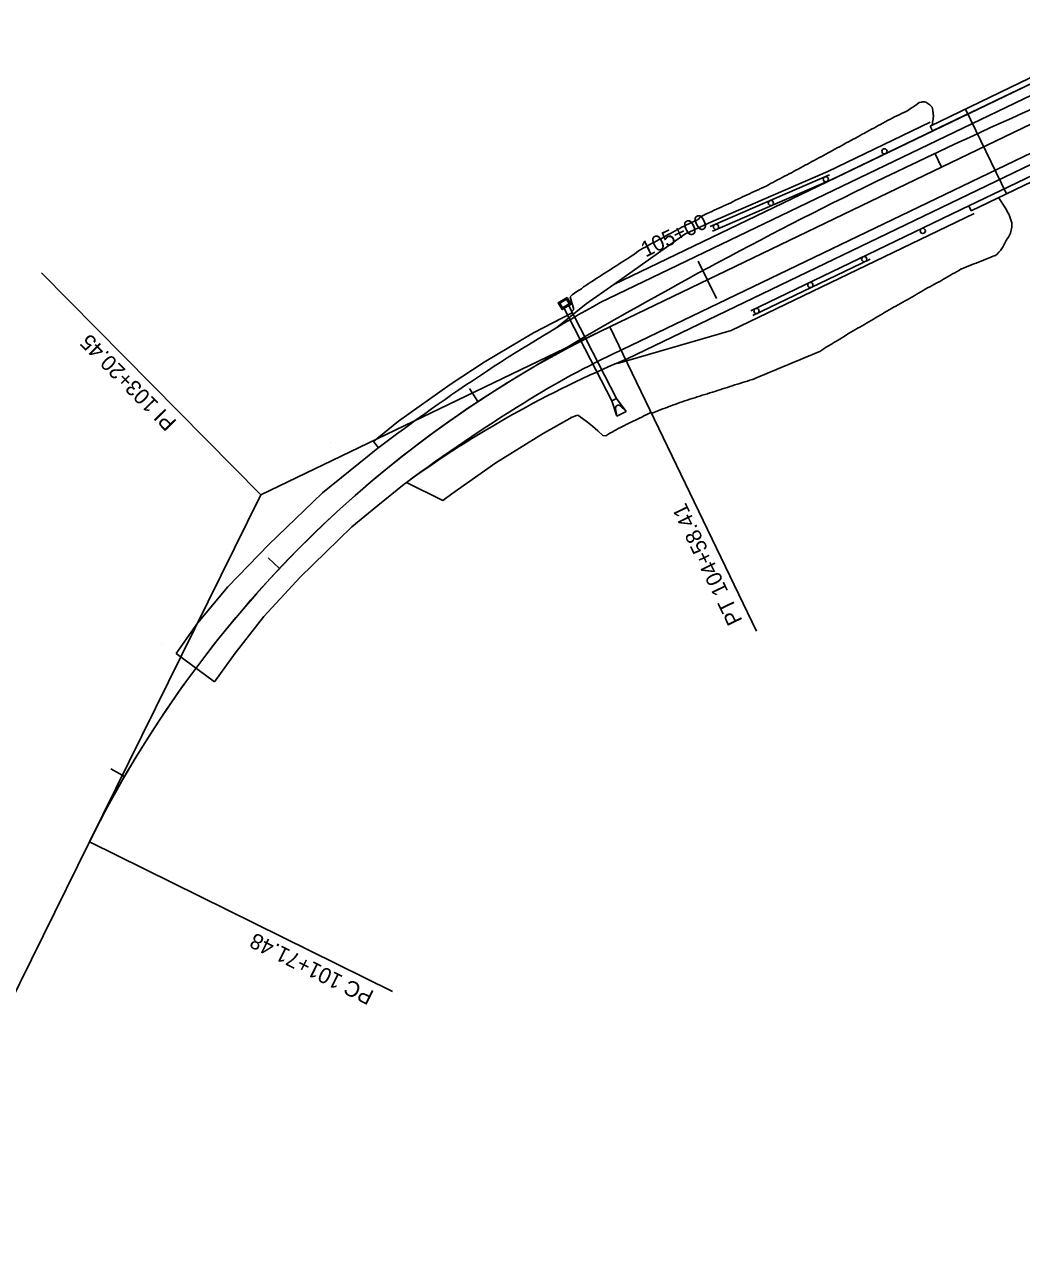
# Model space of a CAD drawing. Extents: x 834421 to 837111, y 495679 to 497078.
# Drawn here: x 835026.1 to 835409.7, y 496460 to 496928.3 of the extents above; entities that cross this region are included whole.
import ezdxf

# ---------------------------------------------------------------- set-up
doc = ezdxf.new("R2010")
doc.units = 0
for name, color, linetype in [('43', 7, 'Continuous'), ('EXISTING CENTERLINE', 7, 'Continuous'), ('R_Bridge', 7, 'Continuous'), ('R_Drainage', 7, 'Continuous'), ('R_Guardrail', 7, 'Continuous'), ('R_Horz Alg', 7, 'Continuous'), ('R_Horz Alg Annot', 7, 'Continuous'), ('R_Horz Alg Stationing', 7, 'Continuous'), ('R_Proposed Const Limits', 7, 'Continuous'), ('R_Proposed Road', 7, 'Continuous'), ('R_Shld_GR', 7, 'Continuous'), ('R_Shoulder', 7, 'Continuous'), ('Transportation__x002e__STATEWIDE_HIGHWAY_LOGMILES_AHTD_point', 7, 'Continuous')]:
    doc.layers.add(name, color=color, linetype=linetype)

msp = doc.modelspace()

# ---------------------------------------------------------------- linework, layer by layer
at = {"layer": '43'}
for p, q in [((835252.05, 496783.43), (835253.83, 496784.34)), ((835252.05, 496783.43), (835253.96, 496777.53)), ((835253.83, 496784.34), (835257.52, 496779.36)), ((835253.96, 496777.53), (835253.47, 496780.42)), ((835253.96, 496777.53), (835257.52, 496779.36)), ((835257.52, 496779.36), (835255.45, 496781.44))]:
    msp.add_line(p, q, dxfattribs=at)
msp.add_arc((835254.62, 496780.62), 1.17, 44.7462, 189.6864, dxfattribs=at)
at = {"layer": 'EXISTING CENTERLINE'}
msp.add_line((834975.23, 496460.02), (835051.16, 496613.79), dxfattribs=at)
for centre, radius, start, end in [((836126.37, 495283.19), 1762.95, 111.78793, 121.11124), ((835438.89, 496422.34), 432.42, 121.1112, 153.7219)]:
    msp.add_arc(centre, radius, start, end, dxfattribs=at)
at = {"layer": 'R_Bridge'}
for p, q in [((835374.54, 496889.18), (835455.78, 496928.29)), ((835375.46, 496887.26), (835456.71, 496926.37)), ((835403.85, 496863.06), (835388.13, 496895.72)), ((835389.34, 496858.43), (835470.58, 496897.54)), ((835390.26, 496856.51), (835471.51, 496895.62)), ((835375.46, 496887.26), (835374.54, 496889.18)), ((835390.26, 496856.51), (835389.34, 496858.43))]:
    msp.add_line(p, q, dxfattribs=at)
at = {"layer": 'R_Drainage'}
for p, q in [((835235.22, 496820.53), (835253.83, 496784.34)), ((835233.51, 496819.49), (835252.05, 496783.43))]:
    msp.add_line(p, q, dxfattribs=at)
for points in [[(835234.84, 496823.22), (835236.39, 496820.65), (835232.97, 496818.58), (835231.42, 496821.15)], [(835234.67, 496822.53), (835235.71, 496820.82), (835233.14, 496819.27), (835232.11, 496820.98)]]:
    msp.add_lwpolyline(points, close=True, dxfattribs=at)
at = {"layer": 'R_Guardrail'}
for p, q in [((835336.66, 496868.58), (835376.08, 496887.56)), ((835335.79, 496870.39), (835289.87, 496850.5)), ((835336.66, 496868.58), (835290.74, 496848.7)), ((835350.54, 496839.75), (835389.96, 496858.73)), ((835305.48, 496818.06), (835350.54, 496839.75)), ((835306.35, 496816.26), (835351.4, 496837.95))]:
    msp.add_line(p, q, dxfattribs=at)
for centre in [(835356.95, 496879.46), (835334.39, 496868.69), (835313.26, 496859.54), (835292.14, 496850.4), (835371.69, 496848.82), (835349.17, 496837.98), (835328.44, 496828.01), (835307.72, 496818.03)]:
    msp.add_circle(centre, 1, dxfattribs=at)
at = {"layer": 'R_Horz Alg'}
for p, q in [((835251.33, 496811.97), (835458.2, 496911.55)), ((835251.33, 496811.97), (835458.2, 496911.55)), ((834975.23, 496460.02), (835051.15, 496613.79)), ((834975.23, 496460.02), (835051.15, 496613.79))]:
    msp.add_line(p, q, dxfattribs=at)
msp.add_arc((835438.88, 496422.34), 432.42, 115.7042, 153.7222, dxfattribs=at)
msp.add_arc((835438.88, 496422.34), 432.42, 115.7042, 153.7222, dxfattribs=at)
at = {"layer": 'R_Horz Alg Annot'}
for p, q in [((835251.33, 496811.97), (835460.14, 496912.48)), ((834975.23, 496460.02), (835051.15, 496613.79))]:
    msp.add_line(p, q, dxfattribs=at)
for points in [[(835117.1, 496747.36), (835032.67, 496832.64)], [(835051.15, 496613.79), (835117.1, 496747.36), (835251.33, 496811.97)], [(835251.33, 496811.97), (835307.71, 496694.84)], [(835051.15, 496613.79), (835167.71, 496556.23)]]:
    msp.add_lwpolyline(points, dxfattribs=at)
msp.add_arc((835438.88, 496422.34), 432.42, 115.7042, 153.7222, dxfattribs=at)
at = {"layer": 'R_Horz Alg Stationing'}
for points in [[(835376.3, 496878.79), (835378.91, 496873.38)], [(835285.33, 496837.22), (835292.27, 496822.8)], [(835197.26, 496788.17), (835200.56, 496783.17)], [(835119.84, 496723.05), (835124.21, 496718.94)], [(835059.41, 496641.93), (835064.6, 496638.92)]]:
    msp.add_lwpolyline(points, dxfattribs=at)
at = {"layer": 'R_Proposed Const Limits'}
for points in [[(835243.79, 496829), (835244.63, 496829.54), (835245.48, 496830.09), (835246.33, 496830.63), (835247.18, 496831.17), (835248.02, 496831.72), (835248.87, 496832.26), (835249.72, 496832.81), (835250.57, 496833.35), (835251.42, 496833.88), (835252.27, 496834.43), (835253.12, 496834.97), (835253.97, 496835.52), (835254.81, 496836.06), (835255.66, 496836.61), (835256.51, 496837.15), (835257.36, 496837.69), (835258.2, 496838.24), (835259.05, 496838.78), (835259.9, 496839.33), (835260.75, 496839.87), (835261.53, 496840.54), (835262.33, 496841.2), (835263.21, 496841.67), (835264.09, 496842.15), (835264.97, 496842.63), (835265.85, 496843.11), (835266.73, 496843.58), (835267.61, 496844.06), (835268.49, 496844.54), (835269.37, 496845.02), (835270.25, 496845.49), (835271.13, 496845.97), (835272.01, 496846.45), (835272.89, 496846.93), (835273.77, 496847.41), (835274.65, 496847.88), (835275.53, 496848.36), (835276.41, 496848.84), (835277.29, 496849.32), (835278.17, 496849.8), (835278.91, 496850.21), (835279.05, 496850.27), (835279.95, 496850.7), (835280.85, 496851.14), (835281.75, 496851.57), (835282.66, 496852), (835283.56, 496852.43), (835284.46, 496852.87), (835285.36, 496853.3), (835286.11, 496854.05), (835286.92, 496854.67), (835287.68, 496855.04), (835287.82, 496855.11), (835288.73, 496855.52), (835289.64, 496855.93), (835290.55, 496856.35), (835291.46, 496856.76), (835292.37, 496857.18), (835293.28, 496857.59), (835294.19, 496858.01), (835295.1, 496858.43), (835296.01, 496858.84), (835296.92, 496859.26), (835297.83, 496859.67), (835298.74, 496860.09), (835299.6, 496860.61), (835300.5, 496861.04), (835301.41, 496861.46), (835302.32, 496861.87), (835303.23, 496862.29), (835304.14, 496862.7), (835305.05, 496863.12), (835305.96, 496863.54), (835306.87, 496863.95), (835307.78, 496864.37), (835308.68, 496864.79), (835309.06, 496864.96), (835309.59, 496865.21), (835310.5, 496865.62), (835311.41, 496866.04), (835312.28, 496866.54), (835313.16, 496867.03), (835314.04, 496867.49), (835314.93, 496867.96), (835315.81, 496868.42), (835316.7, 496868.89), (835317.59, 496869.35), (835318.47, 496869.82), (835319.36, 496870.29), (835320.24, 496870.75), (835321.13, 496871.22), (835322.01, 496871.69), (835322.9, 496872.15), (835323.78, 496872.62), (835324.66, 496873.09), (835325.53, 496873.6), (835326.4, 496874.09), (835327.29, 496874.56), (835328.17, 496875.02), (835329.06, 496875.49), (835329.95, 496875.95), (835330.83, 496876.42), (835331.72, 496876.89), (835332.47, 496877.28), (835332.6, 496877.36), (835333.48, 496877.84), (835334.35, 496878.32), (835335.23, 496878.81), (835336.11, 496879.29), (835336.98, 496879.78), (835337.86, 496880.26), (835338.74, 496880.74), (835339.62, 496881.22), (835340.5, 496881.7), (835341.38, 496882.18), (835342.26, 496882.65), (835343.14, 496883.13), (835344.02, 496883.61), (835344.9, 496884.09), (835345.78, 496884.56), (835346.66, 496885.04), (835347.54, 496885.52), (835348.42, 496886), (835349.3, 496886.47), (835350.18, 496886.95), (835351.06, 496887.43), (835351.94, 496887.91), (835352.82, 496888.39), (835353.7, 496888.86), (835354.58, 496889.34), (835355.46, 496889.82), (835356.34, 496890.29), (835357.22, 496890.77), (835358.1, 496891.25), (835358.85, 496891.65), (835358.98, 496891.72), (835359.86, 496892.19), (835360.75, 496892.66), (835361.65, 496893.09), (835362.55, 496893.52), (835363.46, 496893.95), (835364.36, 496894.38), (835365.26, 496894.81), (835366.14, 496895.3), (835366.97, 496895.86), (835367.81, 496896.43), (835368.65, 496897), (835369.48, 496897.57), (835370.35, 496898.16)], [(835370.35, 496898.16), (835371.14, 496898.36), (835371.56, 496898.44), (835371.98, 496898.5), (835372.4, 496898.51), (835372.84, 496898.33), (835373.26, 496898.11), (835373.66, 496897.87), (835374.03, 496897.61), (835374.37, 496897.33), (835374.69, 496897.04), (835374.98, 496896.74), (835375.24, 496896.43), (835375.39, 496895.81), (835375.51, 496895.26), (835375.6, 496894.77), (835375.66, 496894.33), (835375.71, 496893.93), (835375.73, 496893.58), (835375.75, 496893.26), (835375.75, 496892.98), (835375.75, 496892.72), (835375.73, 496892.48), (835375.72, 496892.27), (835375.69, 496892.08), (835375.67, 496891.9), (835375.64, 496891.74), (835375.61, 496891.59), (835375.27, 496889.39)], [(835405.74, 496849.1), (835405.92, 496850.31), (835405.96, 496851.12), (835405.94, 496851.92), (835405.74, 496852.74), (835405.45, 496853.53), (835405.15, 496854.28), (835404.86, 496855), (835404.53, 496855.69), (835404.17, 496856.34), (835403.85, 496856.97), (835403.51, 496857.57), (835400.83, 496861.74)], [(835399.65, 496839.41), (835400.33, 496839.94), (835400.95, 496840.62), (835401.53, 496841.33), (835402.06, 496842.06), (835402.55, 496842.81), (835402.99, 496843.57), (835403.38, 496844.34), (835403.73, 496845.12), (835404.19, 496845.81), (835404.64, 496846.48), (835405.03, 496847.2), (835405.36, 496847.95), (835405.74, 496849.1)], [(835267.9, 496778.9), (835268.84, 496779.25), (835269.78, 496779.61), (835270.72, 496779.97), (835271.65, 496780.33), (835272.59, 496780.68), (835273.53, 496781.03), (835274.47, 496781.39), (835275.41, 496781.74), (835276.35, 496782.09), (835277.29, 496782.44), (835278.24, 496782.79), (835279.18, 496783.13), (835280.14, 496783.44), (835281.1, 496783.75), (835282.06, 496784.06), (835283.03, 496784.36), (835283.99, 496784.67), (835284.95, 496784.97), (835285.92, 496785.28), (835286.88, 496785.58), (835287.85, 496785.88), (835288.81, 496786.18), (835289.78, 496786.48), (835290.74, 496786.79), (835291.7, 496787.1), (835292.66, 496787.41), (835293.62, 496787.73), (835294.58, 496788.04), (835295.54, 496788.34), (835296.5, 496788.65), (835297.46, 496788.96), (835298.42, 496789.27), (835299.39, 496789.57), (835300.35, 496789.88), (835301.31, 496790.19), (835302.28, 496790.49), (835303.24, 496790.79), (835304.2, 496791.09), (835305.17, 496791.4), (835306.13, 496791.71), (835306.95, 496791.97), (835307.08, 496792.03), (835308.01, 496792.42), (835308.93, 496792.81), (835309.85, 496793.2), (835310.77, 496793.6), (835311.69, 496793.99), (835312.61, 496794.38), (835313.53, 496794.77), (835314.46, 496795.16), (835315.38, 496795.55), (835316.16, 496795.88), (835316.3, 496795.94), (835317.22, 496796.32), (835318.15, 496796.71), (835319.07, 496797.1), (835319.99, 496797.49), (835320.92, 496797.88), (835321.84, 496798.26), (835322.76, 496798.65), (835323.69, 496799.03), (835324.61, 496799.42), (835325.54, 496799.8), (835326.46, 496800.18), (835327.39, 496800.57), (835328.32, 496800.95), (835329.24, 496801.33), (835330.17, 496801.71), (835331.09, 496802.09), (835332.02, 496802.48), (835332.87, 496803.01), (835333.73, 496803.54), (835334.58, 496804.06), (835335.44, 496804.59), (835336.3, 496805.11), (835337.16, 496805.63), (835337.51, 496805.84), (835338.02, 496806.16), (835338.87, 496806.68), (835339.73, 496807.21), (835340.58, 496807.74), (835341.44, 496808.27), (835342.3, 496808.79), (835343.15, 496809.32), (835344.01, 496809.84), (835344.87, 496810.37), (835345.74, 496810.86), (835346.62, 496811.35), (835347.5, 496811.83), (835348.36, 496812.33), (835349.22, 496812.85), (835350.09, 496813.36), (835350.95, 496813.88), (835351.81, 496814.39), (835352.67, 496814.9), (835353.54, 496815.41), (835354.4, 496815.92), (835355.27, 496816.44), (835356.13, 496816.95), (835356.99, 496817.46), (835357.86, 496817.97), (835358.72, 496818.48), (835359.6, 496818.96), (835360.35, 496819.37), (835360.48, 496819.44), (835361.36, 496819.91), (835362.24, 496820.39), (835363.12, 496820.87), (835363.99, 496821.36), (835364.86, 496821.87), (835365.72, 496822.37), (835366.59, 496822.88), (835367.46, 496823.39), (835368.32, 496823.89), (835369.19, 496824.4), (835370.06, 496824.9), (835370.92, 496825.41), (835371.79, 496825.92), (835372.66, 496826.42), (835373.54, 496826.9), (835374.42, 496827.37), (835375.3, 496827.85), (835376.18, 496828.32), (835377.06, 496828.8), (835377.94, 496829.28), (835378.82, 496829.75), (835379.69, 496830.25), (835380.56, 496830.75), (835381.43, 496831.25), (835382.3, 496831.75), (835383.16, 496832.26), (835384.03, 496832.76), (835384.9, 496833.26), (835385.77, 496833.76), (835386.51, 496834.19), (835386.64, 496834.25), (835387.58, 496834.62), (835388.51, 496834.99), (835389.44, 496835.36), (835390.37, 496835.73), (835391.3, 496836.1), (835392.24, 496836.46), (835393.17, 496836.83), (835394.1, 496837.2), (835395.03, 496837.57), (835395.96, 496837.94), (835396.9, 496838.31), (835397.83, 496838.68), (835398.76, 496839.05), (835399.65, 496839.41)], [(835236.85, 496817.29), (835236.66, 496817.79), (835237.41, 496818.58), (835236.09, 496823.47), (835236.87, 496824.23), (835237.69, 496824.93), (835238.57, 496825.48), (835239.46, 496826.03), (835240.35, 496826.59), (835241.18, 496827.27), (835242.05, 496827.85), (835242.93, 496828.43), (835243.79, 496829)], [(835236.85, 496817.29), (835222, 496809.59), (835202.92, 496798.36), (835189.89, 496789.77), (835169.98, 496775.58), (835160.35, 496767.82), (835162.32, 496765.38)], [(835236.29, 496777.03), (835237.2, 496777.34), (835238.12, 496777.63), (835239.04, 496777.93), (835240.83, 496776.66), (835242.67, 496775.27), (835244.58, 496773.75), (835246.63, 496771.96), (835248.67, 496770.15), (835249.77, 496770.05), (835250.56, 496770.51), (835251.35, 496770.97), (835252.14, 496771.44), (835252.93, 496771.9), (835253.72, 496772.35), (835254.52, 496772.81), (835255.34, 496773.22), (835256.16, 496773.63), (835256.98, 496774.03), (835257.8, 496774.43), (835258.51, 496774.77), (835258.63, 496774.83), (835259.45, 496775.23), (835260.28, 496775.62), (835261.11, 496776.01), (835261.93, 496776.41), (835262.75, 496776.82), (835263.57, 496777.22), (835264.39, 496777.63), (835265.22, 496778.03), (835266.04, 496778.42), (835266.87, 496778.82), (835267.9, 496778.9)], [(835236.75, 496777.18), (835225.68, 496770.86), (835207.46, 496759.63), (835190.56, 496747.64), (835187.12, 496745.17), (835173.05, 496752.07)]]:
    msp.add_lwpolyline(points, dxfattribs=at)
at = {"layer": 'R_Proposed Road'}
for p, q in [((835247.52, 496821.24), (835453.86, 496920.56)), ((835256.19, 496803.22), (835464.47, 496903.47)), ((835256.19, 496803.22), (835462.4, 496902.48)), ((835256.19, 496803.22), (835255.21, 496802.76)), ((835084.47, 496686.33), (835099.25, 496675.32))]:
    msp.add_line(p, q, dxfattribs=at)
for points in [[(835084.47, 496686.33), (835092.73, 496697.98), (835104.3, 496711.93), (835120.13, 496728.17), (835130.43, 496738.11), (835140.74, 496748.06), (835151.48, 496756.68), (835162.08, 496765.2)], [(835099.25, 496675.32), (835107.24, 496686.38), (835118.17, 496700.54), (835132.21, 496715.6), (835142.12, 496725.26), (835152.03, 496734.93), (835162.08, 496743.17), (835172.13, 496751.41), (835173.05, 496752.07)]]:
    msp.add_lwpolyline(points, dxfattribs=at)
for centre, radius, start, end in [((835597.34, 496194.92), 717.4, 119.18451, 127.35186), ((835403.47, 496485.71), 350, 115.0625, 121.9342), ((835599.34, 496171.45), 720.31, 121.93416, 126.28612)]:
    msp.add_arc(centre, radius, start, end, dxfattribs=at)
at = {"layer": 'R_Shld_GR'}
for p, q in [((835335.14, 496871.74), (835374.56, 496890.71)), ((835335.14, 496871.74), (835289.22, 496851.85)), ((835297.99, 496810.57), (835391.47, 496855.57)), ((835289.22, 496851.85), (835280.21, 496847.52)), ((835280.21, 496847.52), (835252.86, 496828.25)), ((835297.99, 496810.57), (835254.19, 496797.81))]:
    msp.add_line(p, q, dxfattribs=at)
at = {"layer": 'R_Shoulder'}
for p, q in [((835252.86, 496828.25), (835454.06, 496925.1)), ((835257.93, 496799.61), (835464.14, 496898.87)), ((835252.86, 496828.25), (835242.21, 496820.74)), ((835230.88, 496811.67), (835242.21, 496820.74)), ((835257.93, 496799.61), (835257.39, 496799.39))]:
    msp.add_line(p, q, dxfattribs=at)
msp.add_arc((835419.58, 496411.51), 420.42, 112.6923, 125.9006, dxfattribs=at)
at = {"layer": 'Transportation__x002e__STATEWIDE_HIGHWAY_LOGMILES_AHTD_point'}
for p, q in [((835321.47, 496862.68), (835321.47, 496862.68)), ((835229.48, 496820.09), (835229.48, 496820.09)), ((835143.85, 496767.43), (835143.85, 496767.43)), ((835078.8, 496690.19), (835078.8, 496690.19)), ((835040.49, 496596.16), (835040.49, 496596.16))]:
    msp.add_line(p, q, dxfattribs=at)

# ---------------------------------------------------------------- texts
at = {"layer": 'R_Horz Alg Annot'}
for s, rotation, p in [('PI 103+20.45', 134.7132, (835084.97, 496775.54)), ('PT 104+58.41', 115.7042, (835302.41, 496698.94)), ('PC 101+71.48', 153.7222, (835161, 496556.2))]:
    msp.add_text(s, height=6, rotation=rotation, dxfattribs=at).set_placement(p)
at = {"layer": 'R_Horz Alg Stationing'}
msp.add_text('105+00', height=6, rotation=25.7042, dxfattribs=at).set_placement((835265.09, 496838.58))

doc.saveas('drawing.dxf')
